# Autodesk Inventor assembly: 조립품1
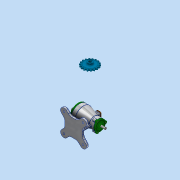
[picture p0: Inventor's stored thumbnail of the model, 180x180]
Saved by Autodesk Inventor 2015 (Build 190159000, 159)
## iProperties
Created: 2018-03
Part Number: 조립품1
Document SubType Name: Assembly
Designer: SCD-A05
Author: SCD-A05
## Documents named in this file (15)
- C:\Users\SCD-A05\Desktop\480308V1002\조립품1.iam
- C:\Users\SCD-A05\Desktop\480308V1002\뒤커버.ipt
- C:\Users\SCD-A05\Desktop\480308V1002\마개.ipt
- C:\Users\SCD-A05\Desktop\480308V1002\베어링-6200.ipt
- C:\Users\SCD-A05\Desktop\480308V1002\베어링-6203.ipt
- C:\Users\SCD-A05\Desktop\480308V1002\본체.ipt
- C:\Users\SCD-A05\Desktop\480308V1002\볼트 M4 x 12.ipt
- 볼트 M4 x 12.ipt
- C:\Users\SCD-A05\Desktop\480308V1002\스프로킷.ipt
- C:\Users\SCD-A05\Desktop\480308V1002\앞커버.ipt
- C:\Users\SCD-A05\Desktop\480308V1002\오일 실 10 20 7.ipt
- C:\Users\SCD-A05\Desktop\480308V1002\오일 실 17 30 8.ipt
- C:\Users\SCD-A05\Desktop\480308V1002\축.ipt
- C:\Users\SCD-A05\Desktop\480308V1002\키 5 x 5.ipt
- 키 5 x 5.ipt
